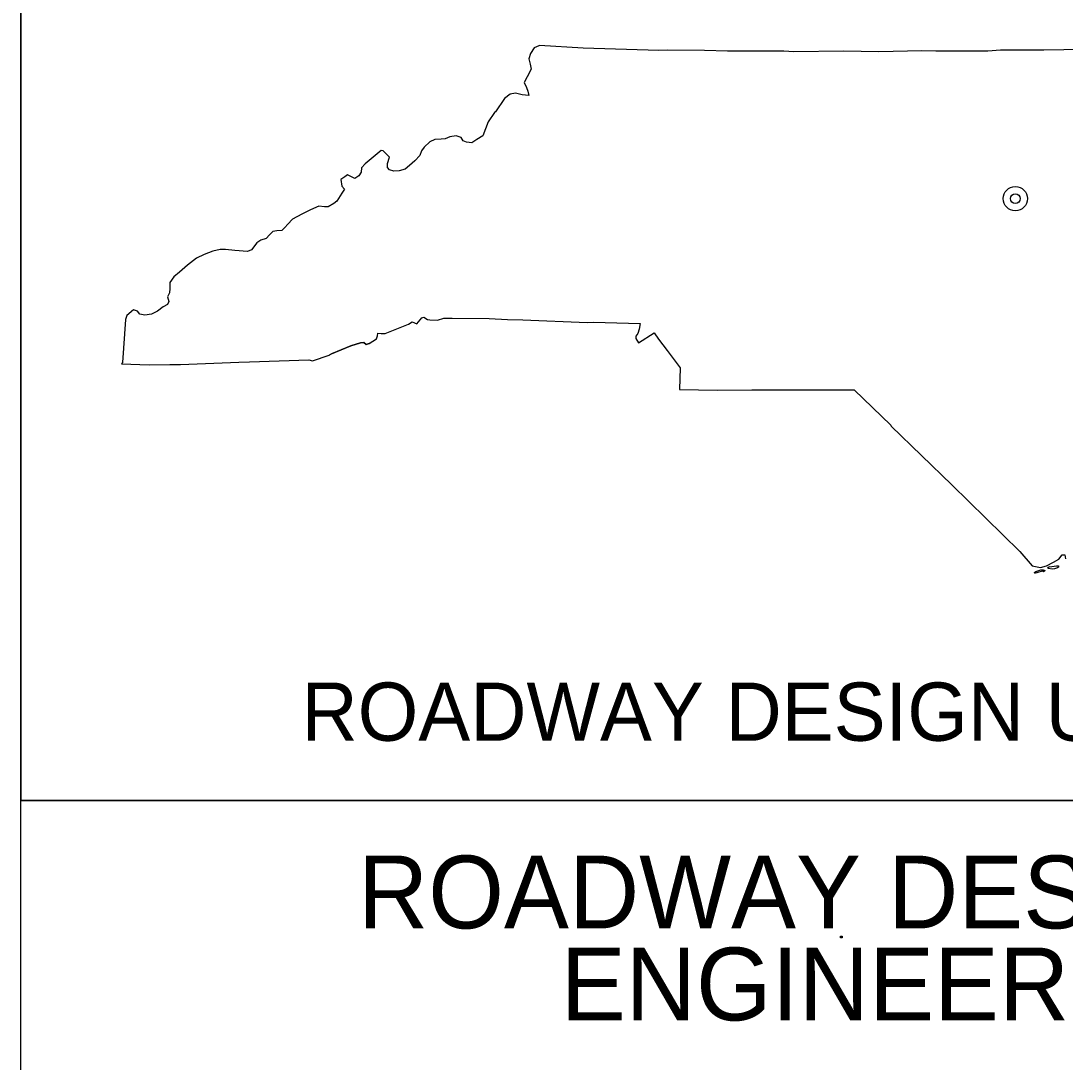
# Model space of a CAD drawing. Extents: x 2.6 to 3.27, y 0.03 to 1.77.
# Drawn here: x 2.6042 to 2.7117, y 1.5591 to 1.6664 of the extents above; entities that cross this region are included whole.
import ezdxf

# ---------------------------------------------------------------- set-up
doc = ezdxf.new("R2010")
doc.units = 0
for name, color, linetype in [('Draft_RDY_Construction_Class_Element', 7, 'Continuous'), ('P_RDY_Dimension_Text', 7, 'Continuous'), ('Sheet_Plan_CELL', 7, 'Continuous')]:
    doc.layers.add(name, color=color, linetype=linetype)

msp = doc.modelspace()

# ---------------------------------------------------------------- linework, layer by layer
at = {"layer": 'Draft_RDY_Construction_Class_Element'}
msp.add_line((2.60416, 0.0625), (2.60416, 1.77083), dxfattribs=at)
msp.add_lwpolyline([(2.60416, 1.70763), (2.60416, 1.58605), (2.77082, 1.58605), (2.77082, 1.70763)], close=True, dxfattribs=at)
at = {"layer": 'P_RDY_Dimension_Text'}
for radius in [0.00125, 0.0005]:
    msp.add_circle((2.70662, 1.64806), radius, dxfattribs=at)
at = {"layer": 'Sheet_Plan_CELL'}
msp.add_line((2.77082, 1.58605), (2.60416, 1.58605), dxfattribs=at)
for points in [[(2.716, 1.66344), (2.71161, 1.66339), (2.70955, 1.66337), (2.7051, 1.66336), (2.70378, 1.66327), (2.69844, 1.66325), (2.69698, 1.6633), (2.69257, 1.6632), (2.68893, 1.66325), (2.68381, 1.66319), (2.68277, 1.66325), (2.67698, 1.66327), (2.67459, 1.66331), (2.67074, 1.66335), (2.6699, 1.66333), (2.6621, 1.66355), (2.65759, 1.66385), (2.65754, 1.66379), (2.65705, 1.6636), (2.65665, 1.66303), (2.6565, 1.66248), (2.65664, 1.66193), (2.65673, 1.6614), (2.65634, 1.66062), (2.65603, 1.66002), (2.65626, 1.65951), (2.6564, 1.65915), (2.6565, 1.6587), (2.65581, 1.65875), (2.65512, 1.65893), (2.65457, 1.65882), (2.654, 1.65837), (2.65305, 1.657), (2.65297, 1.65692), (2.65229, 1.65596), (2.65175, 1.65452), (2.65112, 1.65415), (2.65062, 1.65382), (2.65007, 1.65387), (2.64974, 1.65403), (2.64951, 1.65435), (2.649, 1.65453), (2.64836, 1.65443), (2.64787, 1.65422), (2.64745, 1.65418), (2.64682, 1.65416), (2.6463, 1.65391), (2.6457, 1.65335), (2.64545, 1.65299), (2.64527, 1.65251), (2.64476, 1.65194), (2.64419, 1.65149), (2.64375, 1.65111), (2.64313, 1.65093), (2.64259, 1.65088), (2.64215, 1.65103), (2.64193, 1.65128), (2.64193, 1.65167), (2.64213, 1.65233), (2.64149, 1.653), (2.64127, 1.65302), (2.63964, 1.65163), (2.63927, 1.65124), (2.63921, 1.65079), (2.63898, 1.65041), (2.63858, 1.65014), (2.63782, 1.65053), (2.63754, 1.65031), (2.63713, 1.65002), (2.63724, 1.64935), (2.6375, 1.64904), (2.63724, 1.64862), (2.63672, 1.6478), (2.6364, 1.64756)], [(2.6364, 1.64756), (2.63583, 1.64722), (2.63544, 1.64722), (2.63487, 1.64729), (2.634, 1.64691), (2.63311, 1.64647), (2.63216, 1.64595), (2.63166, 1.64544), (2.63134, 1.64507), (2.63105, 1.64478), (2.63054, 1.64473), (2.63012, 1.64469), (2.62978, 1.64434), (2.62942, 1.64397), (2.62887, 1.64379), (2.62847, 1.64349), (2.62791, 1.64279), (2.6275, 1.64261), (2.62622, 1.64271), (2.62523, 1.64282), (2.6247, 1.64283), (2.62392, 1.64264), (2.62306, 1.64231), (2.62226, 1.64192), (2.62133, 1.64121), (2.6205, 1.64049), (2.61992, 1.63999), (2.61949, 1.63942), (2.61951, 1.63881), (2.61946, 1.63834), (2.61926, 1.63794), (2.61939, 1.63747), (2.61926, 1.63715), (2.61882, 1.6369), (2.61823, 1.63647), (2.61762, 1.63615), (2.61693, 1.63605), (2.61641, 1.63615), (2.61618, 1.63646), (2.61578, 1.63659), (2.61508, 1.63602), (2.61494, 1.63562), (2.61463, 1.63117), (2.61453, 1.63104), (2.61736, 1.63093), (2.6195, 1.63097), (2.62061, 1.63098), (2.6266, 1.6312), (2.6277, 1.63126), (2.63384, 1.63144), (2.63422, 1.63135), (2.63593, 1.63193), (2.63617, 1.63206), (2.63814, 1.63289), (2.63914, 1.63319), (2.63948, 1.63324), (2.63973, 1.63303), (2.64004, 1.63315), (2.64081, 1.63362), (2.64089, 1.63393), (2.64095, 1.63421), (2.64129, 1.63417), (2.6417, 1.63415), (2.64256, 1.63451), (2.6441, 1.63514), (2.64447, 1.63536), (2.64497, 1.63516), (2.64546, 1.63578), (2.64568, 1.63584), (2.64604, 1.63562), (2.64631, 1.63559), (2.6471, 1.63553), (2.64772, 1.63575), (2.64859, 1.63573), (2.6524, 1.6357), (2.65429, 1.63561), (2.65586, 1.63559), (2.6625, 1.6353), (2.66317, 1.63534), (2.66798, 1.6352), (2.66787, 1.63461), (2.66774, 1.63418), (2.66752, 1.63389), (2.66753, 1.63364), (2.66781, 1.6332), (2.6694, 1.63424), (2.66986, 1.63359), (2.67074, 1.63243), (2.6721, 1.63062), (2.67203, 1.62838), (2.67594, 1.62832), (2.67946, 1.62837), (2.68616, 1.62835), (2.68975, 1.62837), (2.69002, 1.62835), (2.69378, 1.62473), (2.69381, 1.6246), (2.70009, 1.61856), (2.70708, 1.6117), (2.70835, 1.61024)], [(2.64004, 1.63315), (2.63973, 1.63303), (2.63948, 1.63324), (2.63914, 1.63319), (2.63814, 1.63289), (2.63617, 1.63206), (2.63593, 1.63193)], [(2.70835, 1.61024), (2.70922, 1.61005), (2.70982, 1.61022), (2.71054, 1.61059), (2.71109, 1.61092), (2.71144, 1.61136), (2.71173, 1.61135), (2.7118, 1.61094)], [(2.70859, 1.60955), (2.70874, 1.60964), (2.70903, 1.60976), (2.70923, 1.60982), (2.70936, 1.60983), (2.70947, 1.60981), (2.70959, 1.60978), (2.70965, 1.60975), (2.70966, 1.60972), (2.70965, 1.6097), (2.70951, 1.60962), (2.70948, 1.60963), (2.70945, 1.60966), (2.70932, 1.60963), (2.70905, 1.60958), (2.70882, 1.60952), (2.70868, 1.60948), (2.70863, 1.60948), (2.7086, 1.60951), (2.70859, 1.60955)], [(2.71015, 1.61014), (2.71087, 1.61024), (2.71101, 1.61023), (2.71108, 1.61021), (2.71106, 1.6101), (2.71096, 1.61002), (2.71065, 1.6099), (2.71042, 1.60987), (2.71005, 1.60996), (2.70995, 1.61001), (2.71001, 1.61009), (2.71017, 1.61016)]]:
    msp.add_lwpolyline(points, dxfattribs=at)
msp.add_circle((2.68869, 1.57198), 0.0001, dxfattribs=at)

# ---------------------------------------------------------------- texts
for s, height, p in [('ROADWAY DESIGN UNIT', 0.006, (2.63307, 1.5922)), ('ROADWAY DESIGN', 0.0075, (2.63889, 1.57287)), ('ENGINEER', 0.0075, (2.65979, 1.56339))]:
    msp.add_text(s, height=height, rotation=0, dxfattribs=at).set_placement(p)

doc.saveas('drawing.dxf')
